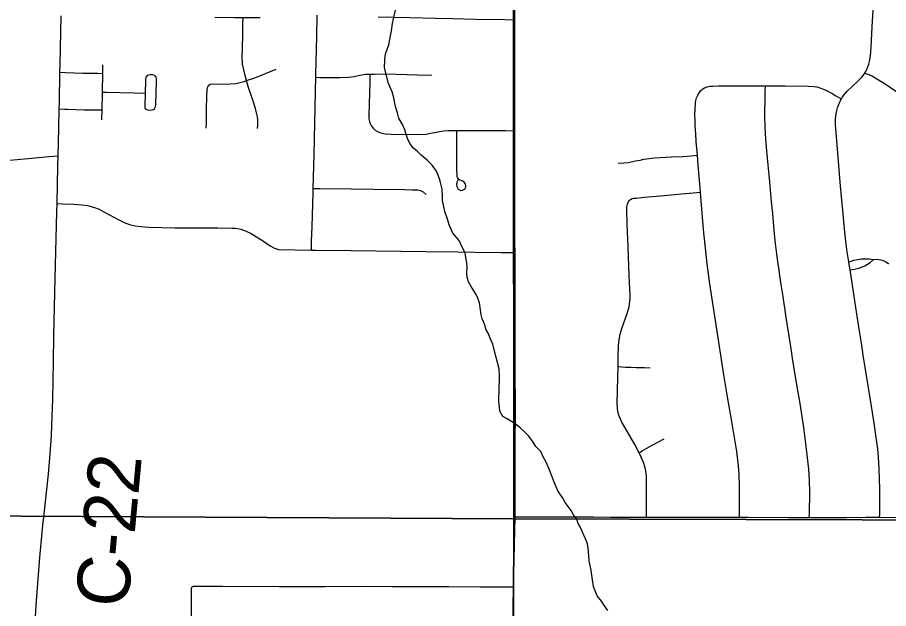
# Model space of a CAD drawing. Extents: x 0 to 34, y 0 to 22.
# Drawn here: x 18.724 to 19.665, y 14.541 to 15.179 of the extents above; entities that cross this region are included whole.
import ezdxf

# ---------------------------------------------------------------- set-up
doc = ezdxf.new("R2010")
doc.units = 0
for name, color, linetype in [('GM_X_City_Street', 7, 'Continuous'), ('GM_X_County_Road', 7, 'Continuous'), ('GM_X_County_Road_Text', 7, 'Continuous'), ('GM_X_Minor_River', 7, 'Continuous'), ('GM_X_Section', 7, 'Continuous')]:
    doc.layers.add(name, color=color, linetype=linetype)

msp = doc.modelspace()

# ---------------------------------------------------------------- linework, layer by layer
at = {"layer": 'GM_X_City_Street'}
for points in [[(18.93745, 15.17963), (18.95843, 15.17937), (18.96787, 15.17929), (18.97696, 15.17921), (18.98613, 15.17949)], [(18.98347, 15.05971), (18.98363, 15.06282), (18.98375, 15.06905), (18.98341, 15.07214), (18.98278, 15.07516), (18.98113, 15.08114), (18.97831, 15.09002), (18.9735, 15.10483), (18.9717, 15.11122), (18.97012, 15.11682), (18.96729, 15.12893), (18.96707, 15.13202), (18.96704, 15.13512), (18.96745, 15.16003), (18.96772, 15.17249), (18.96787, 15.17929)], [(19.04158, 14.92834), (19.04181, 14.93795), (19.04239, 14.95335), (19.04343, 14.99058), (19.04353, 14.99493), (19.04445, 15.0311), (19.04611, 15.09961), (19.04631, 15.11479), (19.04641, 15.11829), (19.0475, 15.15876), (19.04793, 15.18198)], [(19.11359, 15.18026), (19.14776, 15.1793), (19.17568, 15.17858), (19.19437, 15.17836), (19.21923, 15.17765), (19.25026, 15.17708), (19.26103, 15.17687)], [(18.81552, 15.06902), (18.8157, 15.07966), (18.81599, 15.09704), (18.81603, 15.09886), (18.81645, 15.11907), (18.81664, 15.12817)], [(18.77026, 15.12029), (18.77613, 15.12002), (18.78552, 15.11957), (18.79492, 15.11939), (18.80746, 15.11919), (18.81058, 15.11915), (18.81645, 15.11907)], [(18.92815, 15.05975), (18.92833, 15.06559), (18.92854, 15.08111), (18.92885, 15.09331), (18.92913, 15.10255), (18.93, 15.10549), (18.93227, 15.10746), (18.93532, 15.1078), (18.94455, 15.10731), (18.95379, 15.10762), (18.95992, 15.10822), (18.96296, 15.10876), (18.96891, 15.11028), (18.9717, 15.11122), (18.9806, 15.11421), (19.0035, 15.12372)], [(19.04631, 15.11479), (19.05067, 15.11463), (19.05378, 15.1147), (19.0724, 15.1146), (19.08168, 15.11506), (19.08784, 15.11568), (19.09392, 15.11714), (19.09991, 15.11812), (19.1047, 15.11818), (19.10936, 15.11825), (19.12177, 15.11844), (19.15591, 15.11766), (19.17141, 15.11698)], [(18.81603, 15.09886), (18.82044, 15.09874), (18.85049, 15.09791), (18.86229, 15.09767), (18.86177, 15.08405), (18.86191, 15.08219), (18.86235, 15.08112), (18.8633, 15.08026), (18.86478, 15.07969), (18.86759, 15.07951), (18.86991, 15.07962), (18.87102, 15.07992), (18.87214, 15.08088), (18.87288, 15.08214), (18.87336, 15.08371), (18.87356, 15.08517), (18.87406, 15.09788), (18.87437, 15.11015), (18.87433, 15.11337), (18.87411, 15.11498), (18.87342, 15.11593), (18.87278, 15.11652), (18.87178, 15.11708), (18.87005, 15.11736), (18.86749, 15.11741), (18.86576, 15.11716), (18.86445, 15.11666), (18.86347, 15.11557), (18.86306, 15.11488), (18.86273, 15.11404), (18.86261, 15.11323), (18.86255, 15.11092), (18.86229, 15.09767)], [(19.1047, 15.11818), (19.10449, 15.11019), (19.10352, 15.07315), (19.10367, 15.07014), (19.10417, 15.06724), (19.1051, 15.06486), (19.10649, 15.06218), (19.10824, 15.0598), (19.11038, 15.05789), (19.11287, 15.05632), (19.1156, 15.05511), (19.11839, 15.05435), (19.12135, 15.05383), (19.12761, 15.05339), (19.15547, 15.05318), (19.16551, 15.05358), (19.1706, 15.05444), (19.17984, 15.05649), (19.18449, 15.05718), (19.18919, 15.05736), (19.19842, 15.05752), (19.20453, 15.05748), (19.25094, 15.05734), (19.26103, 15.05716)], [(19.50347, 14.64002), (19.50352, 14.64385), (19.50368, 14.65554), (19.50362, 14.67373), (19.50326, 14.68616), (19.50256, 14.69546), (19.50063, 14.71087), (19.49557, 14.74123), (19.49041, 14.77211), (19.48683, 14.7936), (19.48211, 14.82432), (19.47173, 14.89185), (19.46874, 14.91334), (19.46477, 14.95042), (19.46216, 14.98139), (19.46139, 14.99086), (19.46035, 15.00369), (19.45902, 15.02014), (19.45817, 15.03067), (19.45683, 15.04569), (19.45636, 15.05375), (19.45584, 15.06263), (19.45565, 15.06817), (19.45543, 15.07441), (19.45564, 15.0806), (19.45611, 15.0868), (19.45657, 15.08986), (19.45724, 15.09249), (19.4585, 15.09569), (19.46027, 15.09824), (19.46168, 15.10022), (19.46414, 15.10242)], [(19.46414, 15.10242), (19.46592, 15.10355), (19.4687, 15.1044), (19.47175, 15.10508), (19.47483, 15.10542), (19.48105, 15.10558), (19.49976, 15.10549), (19.52387, 15.10547), (19.53171, 15.10547), (19.54038, 15.10546), (19.5529, 15.10566), (19.57787, 15.10541), (19.58409, 15.10493), (19.58692, 15.10439), (19.59014, 15.10347), (19.59593, 15.10112), (19.60427, 15.09685), (19.60699, 15.0953), (19.61362, 15.09152)], [(19.57896, 14.6397), (19.57902, 14.64355), (19.57937, 14.66712), (19.57919, 14.67958), (19.57845, 14.692), (19.57682, 14.70744), (19.57459, 14.72545), (19.57312, 14.73664), (19.57046, 14.75353), (19.56898, 14.76273), (19.56561, 14.78272), (19.56226, 14.80256), (19.56088, 14.81177), (19.55897, 14.8241), (19.55377, 14.85783), (19.55275, 14.86395), (19.55139, 14.87296), (19.5506, 14.87812), (19.54862, 14.89125), (19.5472, 14.90056), (19.54629, 14.90651), (19.5452, 14.9136), (19.54389, 14.92395), (19.54258, 14.9353), (19.54113, 14.94937), (19.53946, 14.96798), (19.53826, 14.98037), (19.53624, 15.00204), (19.53306, 15.03513), (19.53197, 15.04853), (19.53114, 15.06095), (19.53092, 15.07339), (19.53121, 15.09513), (19.53143, 15.09959), (19.53171, 15.10547)], [(18.76944, 15.08078), (18.77532, 15.08056), (18.77831, 15.08045), (18.79628, 15.07984), (18.81126, 15.07971), (18.8157, 15.07966)], [(19.19998, 15.00463), (19.19926, 15.00306), (19.19867, 15.00166), (19.19841, 15.0006), (19.19829, 14.99954), (19.19858, 14.99687), (19.19922, 14.99539), (19.20015, 14.99416), (19.20146, 14.99318), (19.20286, 14.99272), (19.20473, 14.99288), (19.20609, 14.99356), (19.20719, 14.99424), (19.20791, 14.99542), (19.20833, 14.9967), (19.20829, 14.9981), (19.20795, 14.99937), (19.20723, 15.00072), (19.20638, 15.00166), (19.20511, 15.00259), (19.20206, 15.00382), (19.20078, 15.00467), (19.19993, 15.00543), (19.19919, 15.00663), (19.19898, 15.00743), (19.19852, 15.01697), (19.19844, 15.0507), (19.19842, 15.05752)], [(18.51527, 14.99517), (18.52086, 14.9997), (18.53382, 15.01246), (18.53988, 15.01959), (18.54263, 15.02163), (18.54607, 15.02236), (18.5494, 15.02148), (18.5578, 15.01747), (18.56362, 15.01559), (18.56962, 15.01427), (18.57572, 15.01346), (18.58186, 15.01313), (18.58802, 15.01325), (18.60659, 15.01477), (18.64065, 15.01806), (18.69946, 15.02377), (18.7397, 15.02761), (18.75831, 15.02929), (18.76829, 15.03019)], [(19.37274, 15.02212), (19.37871, 15.02235), (19.38381, 15.02301), (19.39154, 15.02449), (19.39645, 15.02555), (19.40024, 15.02637), (19.40356, 15.02696), (19.40848, 15.02753), (19.41193, 15.02793), (19.41787, 15.02836), (19.4301, 15.02883), (19.44232, 15.02939), (19.45145, 15.03013), (19.45817, 15.03067)], [(19.04353, 14.99493), (19.05083, 14.99468), (19.08446, 14.99442), (19.10906, 14.99392), (19.1422, 14.99367), (19.14987, 14.99342), (19.1563, 14.99329), (19.15927, 14.99255), (19.16211, 14.99119), (19.16557, 14.98847)], [(19.40323, 14.64004), (19.40323, 14.64374), (19.40325, 14.65015), (19.40325, 14.65558), (19.40326, 14.66216), (19.40326, 14.66758), (19.40328, 14.67474), (19.40325, 14.68058), (19.40308, 14.68403), (19.40292, 14.68716), (19.40253, 14.69016), (19.40189, 14.6932), (19.40008, 14.69911), (19.39762, 14.70479), (19.39516, 14.7096), (19.39057, 14.71857), (19.38286, 14.73199), (19.37669, 14.74272), (19.37412, 14.74834), (19.37315, 14.75126), (19.37244, 14.75427), (19.37201, 14.75733), (19.37176, 14.76351), (19.3719, 14.77588), (19.37233, 14.79135), (19.37254, 14.80248), (19.37274, 14.81301), (19.37315, 14.82537), (19.37377, 14.83151), (19.37493, 14.83757), (19.37658, 14.84352), (19.38289, 14.86098), (19.38452, 14.86694), (19.38507, 14.86998), (19.38541, 14.87306), (19.38552, 14.87616), (19.38545, 14.87912), (19.38467, 14.90077), (19.38331, 14.9317), (19.3824, 14.95642), (19.382, 14.97186), (19.38219, 14.97494), (19.3827, 14.97799), (19.38388, 14.98083), (19.38489, 14.98203), (19.38603, 14.98303), (19.38769, 14.984), (19.38949, 14.98433), (19.39196, 14.98453), (19.40117, 14.98554), (19.42272, 14.98738), (19.4412, 14.9891), (19.45354, 14.99018), (19.46139, 14.99086)], [(18.76714, 14.97859), (18.77267, 14.97836), (18.78501, 14.97785), (18.79388, 14.97718), (18.80006, 14.97632), (18.80642, 14.97478), (18.8126, 14.97237), (18.81769, 14.96977), (18.83388, 14.9608), (18.83948, 14.95819), (18.84526, 14.95607), (18.85124, 14.95457), (18.85734, 14.95366), (18.86657, 14.95305), (18.89434, 14.95251), (18.91904, 14.95249), (18.94067, 14.95236), (18.95612, 14.95206), (18.95921, 14.95187), (18.96227, 14.95149), (18.96529, 14.95087), (18.96824, 14.94998), (18.97111, 14.94885), (18.97664, 14.94608), (18.98985, 14.93808), (18.99724, 14.933), (19.0017, 14.93042), (19.006, 14.92904)], [(19.006, 14.92904), (19.04158, 14.92834), (19.04682, 14.92824), (19.08425, 14.92796), (19.16537, 14.92689), (19.19969, 14.92644), (19.21841, 14.92623), (19.24652, 14.92582), (19.25277, 14.92562), (19.26133, 14.92567)], [(19.62163, 14.91562), (19.62398, 14.91637), (19.62717, 14.91726), (19.63091, 14.91811), (19.63545, 14.91876), (19.63983, 14.91885), (19.64406, 14.9187), (19.6484, 14.91816)], [(19.62301, 14.90715), (19.62517, 14.9075), (19.62777, 14.90785), (19.63091, 14.90859), (19.63335, 14.90917), (19.63604, 14.91023), (19.63894, 14.91147), (19.64174, 14.91295), (19.6447, 14.91492), (19.6484, 14.91816)], [(19.6484, 14.91816), (19.65128, 14.91837), (19.65378, 14.91821), (19.65605, 14.91788), (19.65868, 14.91706), (19.66164, 14.91551), (19.66428, 14.91396), (19.66493, 14.91347)], [(19.37254, 14.80248), (19.38061, 14.80209), (19.38654, 14.8018), (19.39243, 14.80161), (19.40125, 14.80143), (19.40716, 14.80124)], [(19.39516, 14.7096), (19.39864, 14.71155), (19.40619, 14.7158), (19.41548, 14.72091), (19.42244, 14.72474)], [(18.91225, 14.50243), (18.91212, 14.54207), (18.91208, 14.55298), (18.9121, 14.56171), (18.91212, 14.56276), (18.91223, 14.56376), (18.91245, 14.56438), (18.91303, 14.56498), (18.91406, 14.56541), (18.91517, 14.56559), (18.91599, 14.56567), (18.91701, 14.56569), (18.91793, 14.56569), (18.92053, 14.56569), (18.92363, 14.5657), (18.94536, 14.5655), (19.00688, 14.56531), (19.0565, 14.56528), (19.09679, 14.56537), (19.12927, 14.56526), (19.15052, 14.56518), (19.19008, 14.56503), (19.22337, 14.56491), (19.24744, 14.56483), (19.25986, 14.56478)]]:
    msp.add_lwpolyline(points, dxfattribs=at)
at = {"layer": 'GM_X_County_Road'}
for p, q in [((19.25986, 14.56478), (19.26157, 14.64047)), ((19.25823, 14.49256), (19.25986, 14.56478))]:
    msp.add_line(p, q, dxfattribs=at)
for points in [[(19.26103, 15.17687), (19.26088, 15.23499), (19.26086, 15.25143)], [(19.63882, 15.11941), (19.63983, 15.12094), (19.64102, 15.12323), (19.64225, 15.12607), (19.64316, 15.12903), (19.64386, 15.13204), (19.64484, 15.13817), (19.64562, 15.14744), (19.6468, 15.16914), (19.64854, 15.19994), (19.64926, 15.21095), (19.65009, 15.22065), (19.65096, 15.22808), (19.65204, 15.23735)], [(18.76944, 15.08078), (18.76958, 15.08778), (18.77026, 15.12029), (18.77043, 15.12822), (18.77164, 15.18103)], [(19.26103, 15.05716), (19.26116, 15.11997), (19.26106, 15.16971), (19.26103, 15.17687)], [(19.61362, 15.09152), (19.61453, 15.09311), (19.6163, 15.09566), (19.618, 15.09781), (19.62035, 15.10034), (19.62493, 15.10454), (19.63174, 15.11089), (19.63594, 15.11545), (19.63783, 15.11792), (19.63882, 15.11941)], [(19.63882, 15.11941), (19.64316, 15.1177), (19.64711, 15.1159), (19.65179, 15.11327), (19.6596, 15.10832), (19.67239, 15.09983), (19.68288, 15.0935), (19.68725, 15.09118)], [(19.62301, 14.90715), (19.62174, 14.91494), (19.62163, 14.91562), (19.61993, 14.92661), (19.61845, 14.93796), (19.61738, 14.94783), (19.61616, 14.95901), (19.61501, 14.97102), (19.61377, 14.98618), (19.61232, 15.00158), (19.60825, 15.05106), (19.6073, 15.06344), (19.60729, 15.06964), (19.60796, 15.07581), (19.60855, 15.07886), (19.60939, 15.08184), (19.61043, 15.08476), (19.61298, 15.09042), (19.61362, 15.09152)], [(18.76829, 15.03019), (18.76901, 15.05975), (18.76944, 15.08078)], [(19.26133, 14.92567), (19.26128, 14.93656), (19.26119, 15.01736), (19.26108, 15.04845), (19.26103, 15.05716)], [(18.76714, 14.97859), (18.76803, 15.01931), (18.76829, 15.03019)], [(18.76094, 14.72787), (18.76159, 14.73926), (18.7625, 14.76727), (18.76314, 14.80773), (18.76347, 14.83573), (18.76426, 14.86682), (18.76502, 14.89795), (18.76694, 14.96952), (18.76714, 14.97859)], [(19.26163, 14.68955), (19.26162, 14.71577), (19.26169, 14.7562), (19.26157, 14.79974), (19.26148, 14.84639), (19.26133, 14.92567)], [(19.65478, 14.63986), (19.6549, 14.64342), (19.65509, 14.64922), (19.65512, 14.6554), (19.65512, 14.65833), (19.65496, 14.67067), (19.6545, 14.69231), (19.65379, 14.70469), (19.65288, 14.71394), (19.65196, 14.72104), (19.64885, 14.74141), (19.64603, 14.75992), (19.63722, 14.81495), (19.63551, 14.82566), (19.63308, 14.84091), (19.62935, 14.86627), (19.62495, 14.89522), (19.62301, 14.90715)], [(18.75223, 14.63508), (18.75239, 14.63686), (18.7578, 14.6865), (18.75975, 14.7083), (18.76094, 14.72787)], [(19.26157, 14.64047), (19.26159, 14.65088), (19.26163, 14.67846), (19.26163, 14.68955)], [(19.26157, 14.64047), (19.26909, 14.64039), (19.3147, 14.64032), (19.33041, 14.6403), (19.34592, 14.64034), (19.36455, 14.64017), (19.38933, 14.64009), (19.40323, 14.64004)], [(19.40323, 14.64004), (19.42325, 14.63998), (19.48213, 14.64001), (19.50347, 14.64002)], [(19.50347, 14.64002), (19.51314, 14.64002), (19.55658, 14.63978), (19.57896, 14.6397)], [(19.57896, 14.6397), (19.59384, 14.63966), (19.61869, 14.63983), (19.6404, 14.6399), (19.65478, 14.63986)], [(19.65478, 14.63986), (19.68693, 14.63977), (19.70865, 14.63959), (19.74593, 14.63946), (19.77379, 14.63955), (19.78882, 14.63929), (19.80732, 14.63899), (19.829, 14.63914), (19.85229, 14.63875), (19.86549, 14.63867), (19.88085, 14.6385), (19.89321, 14.63852), (19.90548, 14.63864), (19.92357, 14.63873), (19.94566, 14.63911), (19.95435, 14.63918), (19.96478, 14.63891)], [(18.74394, 14.53308), (18.74477, 14.54984), (18.74863, 14.59648), (18.75223, 14.63508)]]:
    msp.add_lwpolyline(points, dxfattribs=at)
at = {"layer": 'GM_X_Minor_River'}
for points in [[(19.2441, 14.7748), (19.24439, 14.78202), (19.24472, 14.7862), (19.24465, 14.79152), (19.24416, 14.80025), (19.24254, 14.80706), (19.24056, 14.81387), (19.23895, 14.82069), (19.23735, 14.82675), (19.2346, 14.83317), (19.23225, 14.83846), (19.22991, 14.84298), (19.22871, 14.84752), (19.22596, 14.85394), (19.22476, 14.85849), (19.2239, 14.86645), (19.22307, 14.87138), (19.22111, 14.87629), (19.21953, 14.88045), (19.2141, 14.88911), (19.21099, 14.89401), (19.20979, 14.89893), (19.20935, 14.9031), (19.20964, 14.91033), (19.20921, 14.9145), (19.20837, 14.92019), (19.20754, 14.92549), (19.20442, 14.93153), (19.2009, 14.9387), (19.19434, 14.94659), (19.19042, 14.95565), (19.18883, 14.96057), (19.18567, 14.97002), (19.18446, 14.97494), (19.18323, 14.98177), (19.18317, 14.98632), (19.18269, 14.99391), (19.18108, 15.00111), (19.17988, 15.00527), (19.17673, 15.01359), (19.17209, 15.01998), (19.16669, 15.02523), (19.16016, 15.03084), (19.15592, 15.03496), (19.15169, 15.03832), (19.14782, 15.04321), (19.14547, 15.04888), (19.14231, 15.05795), (19.13995, 15.064), (19.13606, 15.07078), (19.13446, 15.07646), (19.13247, 15.08327), (19.13045, 15.09274), (19.12884, 15.09918), (19.12492, 15.10824), (19.12052, 15.1249), (19.12078, 15.13401), (19.12146, 15.1401), (19.12514, 15.15003), (19.12692, 15.15955), (19.12799, 15.16488), (19.12903, 15.17287), (19.1301, 15.17782), (19.13226, 15.18735)], [(19.36164, 14.53934), (19.35777, 14.54423), (19.35466, 14.5495), (19.35002, 14.55514), (19.34767, 14.56042), (19.34609, 14.56534), (19.34485, 14.57254), (19.34441, 14.57747), (19.34358, 14.58278), (19.34154, 14.59301), (19.3411, 14.59832), (19.34023, 14.60667), (19.33941, 14.61121), (19.33744, 14.6165), (19.3343, 14.62368), (19.33195, 14.62897), (19.32961, 14.63312), (19.32803, 14.63803), (19.32455, 14.64254), (19.32183, 14.64706), (19.31563, 14.65572), (19.3129, 14.66062), (19.30748, 14.66852), (19.3059, 14.67268), (19.30277, 14.67948), (19.30079, 14.68553), (19.29843, 14.6912), (19.29451, 14.70026), (19.29179, 14.70516), (19.28905, 14.71082), (19.28365, 14.71645), (19.28093, 14.72097), (19.27629, 14.72737), (19.27204, 14.73187), (19.26704, 14.73636), (19.26243, 14.7401), (19.25783, 14.74307), (19.25284, 14.74605), (19.24825, 14.74864), (19.24513, 14.7543), (19.24469, 14.75923), (19.24386, 14.76454), (19.24379, 14.76948), (19.2441, 14.7748)]]:
    msp.add_lwpolyline(points, dxfattribs=at)
at = {"layer": 'GM_X_Section'}
for points in [[(19.25935, 15.65043), (19.25999, 14.63809), (18.26161, 14.6436), (18.23936, 15.65543)], [(20.25544, 15.64755), (20.26215, 14.63524), (19.25999, 14.63809), (19.25935, 15.65043)], [(18.26161, 14.6436), (19.25999, 14.63809), (19.25652, 13.61624), (18.23693, 13.62087), (18.23735, 14.64421)], [(19.25999, 14.63809), (20.26215, 14.63524), (20.2632, 13.61532), (19.25652, 13.61624)]]:
    msp.add_lwpolyline(points, close=True, dxfattribs=at)

# ---------------------------------------------------------------- texts
at = {"layer": 'GM_X_County_Road_Text'}
msp.add_text('C-22', height=0.056818, rotation=84.65691, dxfattribs=at).set_placement((18.84333, 14.54123))

doc.saveas('drawing.dxf')
